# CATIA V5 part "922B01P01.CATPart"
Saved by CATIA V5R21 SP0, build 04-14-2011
Part number: 922B01P01
Bounding box of the stored display mesh (mm): x -17 to 17, y -76.2 to 76.2, z -4.3 to 4.3
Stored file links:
  C:\Users\ALI OZGUN\Desktop\alhan\922B01P01.CATPart
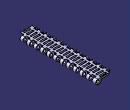
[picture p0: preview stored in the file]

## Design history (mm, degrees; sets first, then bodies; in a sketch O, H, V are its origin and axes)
Body1 (main body)
  Sketch1 on zx-plane, origin (0, 0, 0), H (-1, 0, 0), V (0, 0, 1)
    construction line L1 (-12.7, 0) -> (12.7, 0)
    point P1 (-12.7, 0)
    line L2 (-12.7, 4.3) -> (12.7, 4.3)
    line L3 (12.7, -4.3) -> (-12.7, -4.3)
    arc A1 centre (12.7, 0) radius 4.3 from (12.7, 4.3) to (12.7, -4.3) cw
    arc A2 centre (-12.7, 0) radius 4.3 from (-12.7, -4.3) to (-12.7, 4.3) cw
    distance L1 L2 = 4.3
    length L1 = 25.4
    distance P1 V = 12.7
    coincidence: P1 H
    horizontal: L1 H
    tangency: A1 L2, A2 L2, A1 L3, A2 L3
  Pad1: profile Sketch1, direction (0, 1, 0), length 76.2, mirrored extent
  Sketch2 on face of Pad1 from Sketch1.L2, origin (0, 0, 4.3), H (1, 0, 0), V (0, 1, 0)
    line L1 (-22.3127, -63.5) -> (-9.75, -63.5)
    line L2 (-9.75, -63.5) -> (-9.75, -70.6)
    line L3 (-9.75, -70.6) -> (-22.3127, -70.6)
    line L4 (-22.3127, -70.6) -> (-22.3127, -63.5)
    line L5 (24.6678, -76.95) -> (9.75, -76.95)
    line L6 (9.75, -76.95) -> (9.75, -69.85)
    line L7 (9.75, -69.85) -> (24.6678, -69.85)
    line L8 (24.6678, -69.85) -> (24.6678, -76.95)
    reference projected line E1 (-12.7, -76.2) -> (12.7, -76.2) from edge [start face of Pad1 | face of Pad1 from Sketch1.L2]
    reference projected line E2 (-12.7, -76.2) -> (12.7, -76.2) from edge [start face of Pad1 | face of Pad1 from Sketch1.L2]
    distance L3 E1 = 5.6
    length L4 = 7.1
    distance L7 L5 = 7.1
    distance L5 E2 = 0.75
    distance L2 L6 = 19.5
    distance L2 V = 9.75
    horizontal: L1 H, L3 H, L5 H, L7 H
    vertical: L2 V, L4 V, L6 V, L8 V
  Pocket1: profile Sketch2, direction (0, 0, -1), length 76.2
  RectPattern1: of Pocket1, direction 1 instances 12, spacing 12.7, along axis of face of Pad1 from Sketch1.A2
  Sketch3 on face of Pad1 from Sketch1.L3, origin (0, 0, -4.3), H (1, 0, 0), V (0, -1, 0)
    line L1 (-7, 90.4553) -> (7, 90.4553)
    line L2 (7, 90.4553) -> (7, -88.0088)
    line L3 (7, -88.0088) -> (-7, -88.0088)
    line L4 (-7, -88.0088) -> (-7, 90.4553)
    length L1 = 14
    distance L4 V = 7
    horizontal: L1 H, L3 H
    vertical: L2 V, L4 V
  Pocket2: profile Sketch3, direction (0, 0, 1), length 5.7
  Fillet1: radius 2, on edge [face of Pad1 from Sketch1.L3 | face of Pocket2 from Sketch3.L2]; edge [face of Pad1 from Sketch1.L3 | face of Pocket2 from Sketch3.L4]
  Sketch4 on yz-plane, origin (0, 0, 0), H (0, 1, 0), V (0, 0, 1)
    point P3 (69.85, -4.4)
    point P5 (69.85, -4.4)
    point P7 (57.15, -4.4)
    point P9 (57.15, -4.4)
    point P11 (44.45, -4.4)
    point P13 (44.45, -4.4)
    point P15 (31.75, -4.4)
    point P16 (31.75, -4.4)
    point P18 (19.05, -4.4)
    point P19 (19.05, 1.4)
    point P20 (19.05, -4.4)
    line L1 (-76.2, -4.4) -> (-76.2, 1.4)
    line L2 (-69.85, 1.4) -> (-69.85, -4.4)
    line L3 (-69.85, -4.4) -> (-76.2, -4.4)
    line L4 (-57.15, -4.4) -> (-64.25, -4.4)
    line L5 (-64.25, -4.4) -> (-64.25, 1.4)
    line L6 (-57.15, 1.4) -> (-57.15, -4.4)
    line L7 (-44.45, -4.4) -> (-51.55, -4.4)
    line L8 (-51.55, -4.4) -> (-51.55, 1.4)
    line L9 (-44.45, 1.4) -> (-44.45, -4.4)
    line L10 (-31.75, -4.4) -> (-38.85, -4.4)
    line L11 (-38.85, -4.4) -> (-38.85, 1.4)
    line L12 (-19.05, -4.4) -> (-26.15, -4.4)
    line L13 (-26.15, -4.4) -> (-26.15, 1.4)
    line L14 (-19.05, 1.4) -> (-19.05, -4.4)
    line L15 (-6.35, -4.4) -> (-13.45, -4.4)
    line L16 (-13.45, -4.4) -> (-13.45, 1.4)
    line L17 (-6.35, 1.4) -> (-6.35, -4.4)
    line L18 (6.35, -4.4) -> (-0.75, -4.4)
    line L19 (-0.75, -4.4) -> (-0.75, 1.4)
    line L20 (6.35, 1.4) -> (6.35, -4.4)
    construction line L21 (19.05, -4.4) -> (11.95, -4.4)
    construction line L22 (11.95, -4.4) -> (11.95, 4.4)
    construction line L23 (11.95, 4.4) -> (19.05, 4.4)
    construction line L24 (19.05, 4.4) -> (19.05, -4.4)
    line L25 (19.05, 1.4) -> (19.05, -4.4)
    line L26 (19.05, -4.4) -> (11.95, -4.4)
    line L27 (11.95, -4.4) -> (11.95, 1.4)
    construction line L28 (31.75, -4.4) -> (24.65, -4.4)
    construction line L29 (24.65, -4.4) -> (24.65, 4.4)
    construction line L30 (24.65, 4.4) -> (31.75, 4.4)
    construction line L31 (31.75, 4.4) -> (31.75, -4.4)
    line L32 (31.75, -4.4) -> (24.65, -4.4)
    line L33 (24.65, -4.4) -> (24.65, 1.4)
    line L34 (31.75, 1.4) -> (31.75, -4.4)
    construction line L35 (44.45, -4.4) -> (37.35, -4.4)
    construction line L36 (37.35, -4.4) -> (37.35, 4.4)
    construction line L37 (37.35, 4.4) -> (44.45, 4.4)
    construction line L38 (44.45, 4.4) -> (44.45, -4.4)
    line L39 (44.45, -4.4) -> (37.35, -4.4)
    line L40 (37.35, -4.4) -> (37.35, 1.4)
    line L41 (44.45, 1.4) -> (44.45, -4.4)
    construction line L42 (57.15, -4.4) -> (50.05, -4.4)
    construction line L43 (50.05, -4.4) -> (50.05, 4.4)
    construction line L44 (50.05, 4.4) -> (57.15, 4.4)
    construction line L45 (57.15, 4.4) -> (57.15, -4.4)
    line L46 (57.15, -4.4) -> (50.05, -4.4)
    line L47 (50.05, -4.4) -> (50.05, 1.4)
    line L48 (57.15, 1.4) -> (57.15, -4.4)
    construction line L49 (69.85, -4.4) -> (62.75, -4.4)
    construction line L50 (62.75, -4.4) -> (62.75, 4.4)
    construction line L51 (62.75, 4.4) -> (69.85, 4.4)
    construction line L52 (69.85, 4.4) -> (69.85, -4.4)
    line L53 (69.85, 1.4) -> (69.85, -4.4)
    line L54 (69.85, -4.4) -> (62.75, -4.4)
    line L55 (62.75, -4.4) -> (62.75, 1.4)
    construction line L56 (-76.2, 1.4) -> (76.2, 1.4)
    line L57 (62.75, 1.4) -> (69.85, 1.4)
    line L58 (50.05, 1.4) -> (57.15, 1.4)
    line L59 (37.35, 1.4) -> (44.45, 1.4)
    line L60 (-76.2, 1.4) -> (-69.85, 1.4)
    point P60 (19.05, 1.4)
    line L61 (24.65, 1.4) -> (31.75, 1.4)
    point P61 (24.65, 1.4)
    point P62 (24.65, 1.4)
    point P63 (11.95, 1.4)
    point P64 (6.35, 1.4)
    point P65 (-0.75, 1.4)
    point P66 (-6.35, 1.4)
    point P67 (-13.45, 1.4)
    point P68 (-19.05, 1.4)
    point P69 (-26.15, 1.4)
    point P70 (-38.85, 1.4)
    point P71 (-44.45, 1.4)
    point P72 (-51.55, 1.4)
    point P73 (-57.15, 1.4)
    point P74 (-64.25, 1.4)
    point P75 (-69.85, 1.4)
    line L62 (-64.25, 1.4) -> (-57.15, 1.4)
    line L63 (-51.55, 1.4) -> (-44.45, 1.4)
    line L64 (-38.85, 1.4) -> (-31.75, 1.4)
    line L65 (-26.15, 1.4) -> (-19.05, 1.4)
    line L66 (-13.45, 1.4) -> (-6.35, 1.4)
    line L67 (-0.75, 1.4) -> (6.35, 1.4)
    line L68 (11.95, 1.4) -> (19.05, 1.4)
    line L69 (-31.75, 1.4) -> (-31.75, -4.4)
    coincidence: L24 P60, L29 P61, L60 L61, L56 P62, L56 P63, L56 P64, L56 P65, L56 P66, L56 P67, L56 P68, L56 P69, L56 P70, L56 P71, L56 P72, L56 P73, L56 P74, L56 P75, L60 L62, L62 L63, L63 L64, L64 L65, L65 L66, L66 L67, L67 L68, P3 P5, P7 P9, P11 P13, P15 P16, P18 P20, P19 P60, P61 P62
    vertical: L69 V
  Pocket3: profile Sketch4, direction (1, 0, 0), length 27.8
  Sketch5 on yz-plane, origin (0, 0, 0), H (0, 1, 0), V (0, 0, 1)
    line L1 (-63.5, -4.4) -> (-70.6, -4.4)
    point P1 (-63.5, -4.4)
    point P2 (-70.6, -4.4)
    line L2 (-63.5, 1.4) -> (-63.5, -4.4)
    point P3 (-63.5, 1.4)
    point P4 (-63.5, -4.4)
    line L3 (-70.6, 1.4) -> (-63.5, 1.4)
    point P5 (-70.6, 1.4)
    point P6 (-63.5, 1.4)
    line L4 (-70.6, -4.4) -> (-70.6, 1.4)
    point P7 (-70.6, -4.4)
    point P8 (-70.6, 1.4)
    line L5 (-50.8, 1.4) -> (-50.8, -4.4)
    point P9 (-50.8, 1.4)
    point P10 (-50.8, -4.4)
    line L6 (-57.9, 1.4) -> (-50.8, 1.4)
    point P11 (-57.9, 1.4)
    point P12 (-50.8, 1.4)
    line L7 (-57.9, -4.4) -> (-57.9, 1.4)
    point P13 (-57.9, -4.4)
    point P14 (-57.9, 1.4)
    line L8 (-50.8, -4.4) -> (-57.9, -4.4)
    point P15 (-50.8, -4.4)
    point P16 (-57.9, -4.4)
    line L9 (-38.1, 1.4) -> (-38.1, -4.4)
    point P17 (-38.1, 1.4)
    point P18 (-38.1, -4.4)
    line L10 (-45.2, 1.4) -> (-38.1, 1.4)
    point P19 (-45.2, 1.4)
    point P20 (-38.1, 1.4)
    line L11 (-45.2, -4.4) -> (-45.2, 1.4)
    point P21 (-45.2, -4.4)
    point P22 (-45.2, 1.4)
    line L12 (-38.1, -4.4) -> (-45.2, -4.4)
    point P23 (-38.1, -4.4)
    point P24 (-45.2, -4.4)
    line L13 (-25.4, 1.4) -> (-25.4, -4.4)
    point P25 (-25.4, 1.4)
    point P26 (-25.4, -4.4)
    line L14 (-32.5, 1.4) -> (-25.4, 1.4)
    point P27 (-32.5, 1.4)
    point P28 (-25.4, 1.4)
    line L15 (-32.5, -4.4) -> (-32.5, 1.4)
    point P29 (-32.5, -4.4)
    point P30 (-32.5, 1.4)
    line L16 (-25.4, -4.4) -> (-32.5, -4.4)
    point P31 (-25.4, -4.4)
    point P32 (-32.5, -4.4)
    line L17 (-12.7, 1.4) -> (-12.7, -4.4)
    point P33 (-12.7, 1.4)
    point P34 (-12.7, -4.4)
    line L18 (-19.8, 1.4) -> (-12.7, 1.4)
    point P35 (-19.8, 1.4)
    point P36 (-12.7, 1.4)
    line L19 (-19.8, -4.4) -> (-19.8, 1.4)
    point P37 (-19.8, -4.4)
    point P38 (-19.8, 1.4)
    line L20 (-12.7, -4.4) -> (-19.8, -4.4)
    point P39 (-12.7, -4.4)
    point P40 (-19.8, -4.4)
    line L21 (0, 1.4) -> (0, -4.4)
    point P41 (0, 1.4)
    point P42 (0, -4.4)
    line L22 (-7.1, 1.4) -> (0, 1.4)
    point P43 (-7.1, 1.4)
    point P44 (0, 1.4)
    line L23 (-7.1, -4.4) -> (-7.1, 1.4)
    point P45 (-7.1, -4.4)
    point P46 (-7.1, 1.4)
    line L24 (0, -4.4) -> (-7.1, -4.4)
    point P47 (0, -4.4)
    point P48 (-7.1, -4.4)
    line L25 (12.7, 1.4) -> (12.7, -4.4)
    point P49 (12.7, 1.4)
    point P50 (12.7, -4.4)
    line L26 (5.6, 1.4) -> (12.7, 1.4)
    point P51 (5.6, 1.4)
    point P52 (12.7, 1.4)
    line L27 (5.6, -4.4) -> (5.6, 1.4)
    point P53 (5.6, -4.4)
    point P54 (5.6, 1.4)
    line L28 (12.7, -4.4) -> (5.6, -4.4)
    point P55 (12.7, -4.4)
    point P56 (5.6, -4.4)
    line L29 (18.3, 1.4) -> (25.4, 1.4)
    point P57 (18.3, 1.4)
    point P58 (25.4, 1.4)
    line L30 (18.3, -4.4) -> (18.3, 1.4)
    point P59 (18.3, -4.4)
    point P60 (18.3, 1.4)
    line L31 (25.4, -4.4) -> (18.3, -4.4)
    point P61 (25.4, -4.4)
    point P62 (18.3, -4.4)
    line L32 (25.4, 1.4) -> (25.4, -4.4)
    point P63 (25.4, 1.4)
    point P64 (25.4, -4.4)
    line L33 (38.1, 1.4) -> (38.1, -4.4)
    point P65 (38.1, 1.4)
    point P66 (38.1, -4.4)
    line L34 (31, 1.4) -> (38.1, 1.4)
    point P67 (31, 1.4)
    point P68 (38.1, 1.4)
    line L35 (31, -4.4) -> (31, 1.4)
    point P69 (31, -4.4)
    point P70 (31, 1.4)
    line L36 (38.1, -4.4) -> (31, -4.4)
    point P71 (38.1, -4.4)
    point P72 (31, -4.4)
    line L37 (50.8, 1.4) -> (50.8, -4.4)
    point P73 (50.8, 1.4)
    point P74 (50.8, -4.4)
    line L38 (43.7, 1.4) -> (50.8, 1.4)
    point P75 (43.7, 1.4)
    point P76 (50.8, 1.4)
    line L39 (43.7, -4.4) -> (43.7, 1.4)
    point P77 (43.7, -4.4)
    point P78 (43.7, 1.4)
    line L40 (50.8, -4.4) -> (43.7, -4.4)
    point P79 (50.8, -4.4)
    point P80 (43.7, -4.4)
    line L41 (63.5, 1.4) -> (63.5, -4.4)
    point P81 (63.5, 1.4)
    point P82 (63.5, -4.4)
    line L42 (56.4, 1.4) -> (63.5, 1.4)
    point P83 (56.4, 1.4)
    point P84 (63.5, 1.4)
    line L43 (56.4, -4.4) -> (56.4, 1.4)
    point P85 (56.4, -4.4)
    point P86 (56.4, 1.4)
    line L44 (63.5, -4.4) -> (56.4, -4.4)
    point P87 (63.5, -4.4)
    point P88 (56.4, -4.4)
    line L45 (69.1, 1.4) -> (76.2, 1.4)
    point P89 (69.1, 1.4)
    point P90 (76.2, 1.4)
    line L46 (69.1, -4.4) -> (69.1, 1.4)
    point P91 (69.1, -4.4)
    point P92 (69.1, 1.4)
    line L47 (76.2, -4.4) -> (69.1, -4.4)
    point P93 (76.2, -4.4)
    point P94 (69.1, -4.4)
    line L48 (76.2, 1.4) -> (76.2, -4.4)
    point P95 (76.2, 1.4)
    point P96 (76.2, -4.4)
    distance L2 L4 = 7.1
    distance L7 L5 = 7.1
    coincidence: P96 P93, P95 P90, P94 P91, P92 P89, P88 P85, P87 P82, P86 P83, P84 P81, P80 P77, P79 P74, P78 P75, P76 P73, P72 P69, P71 P66, P70 P67, P68 P65, P64 P61, P63 P58, P62 P59, P60 P57, P56 P53, P55 P50, P54 P51, P52 P49, P48 P45, P47 P42, P46 P43, P44 P41, P40 P37, P39 P34, P38 P35, P36 P33, P32 P29, P31 P26, P30 P27, P28 P25, P24 P21, P23 P18, P22 P19, P20 P17, P16 P13, P15 P10, P14 P11, P12 P9, P8 P5, P7 P2, P6 P3, P4 P1
    fix: L2
  Pocket4: profile Sketch5, direction (-1, 0, 0), length 27.8
  Chamfer1: length 2.5, angle 45, on edge [face of Pocket4 | face of Pocket1 from Sketch2.L6]; edge [face of Pocket4 | face of RectPattern1] (x11); edge [face of RectPattern1 | face of Pocket4] (x11); edge [face of Pocket4 | face of Pocket1 from Sketch2.L2]
  Sketch6 on zx-plane, origin (0, 0, 0), H (-1, 0, 0), V (0, 0, 1)
    circle A1 centre (12.7, 0) radius 2.3
    point P1 (12.7, 0)
    circle A2 centre (-12.7, 0) radius 2.3
    point P2 (-12.7, 0)
    reference projected arc E1 centre (12.7, 0) radius 4.3 from (12.7, -4.3) to (12.7, 4.3) ccw from edge [face of Pocket4 | face of Pad1 from Sketch1.A1]
    reference projected arc E2 centre (-12.7, 0) radius 4.3 from (-12.7, 4.3) to (-12.7, -4.3) ccw from edge [face of Pad1 from Sketch1.A2 | end face of Pad1]
    radius A1 = 2.3
    radius A2 = 2.3
    coincidence: P1 H, P2 H
    concentricity: P1 E1, A2 E2
  Pocket5: profile Sketch6, direction (0, -1, 0), length 97.8, mirrored extent
  Sketch7 on face of Pad1 from Sketch1.L2, origin (0, 0, 4.3), H (1, 0, 0), V (0, 1, 0)
    line L1 (-6.2, -71.4) -> (6.2, -71.4)
    line L2 (6.2, -71.4) -> (6.2, -74.2)
    line L3 (6.2, -74.2) -> (-6.2, -74.2)
    line L4 (-6.2, -74.2) -> (-6.2, -71.4)
    reference projected line E1 (-12.7, -76.2) -> (12.7, -76.2) from edge [start face of Pad1 | face of Pad1 from Sketch1.L2]
    line L5 (-6.2, -65.1) -> (6.2, -65.1)
    line L6 (6.2, -65.1) -> (6.2, -68.4)
    line L7 (6.2, -68.4) -> (-6.2, -68.4)
    line L8 (-6.2, -68.4) -> (-6.2, -65.1)
    distance L3 E1 = 2
    length L1 = 12.4
    distance L1 L3 = 2.8
    distance L5 L7 = 3.3
    distance L7 L1 = 3
    distance L4 V = 6.2
    horizontal: L1 H, L3 H, L5 H, L7 H
    vertical: L2 V, L4 V, L6 V, L8 V
    coincidence: L6 L2, L8 L4
  Pocket6: profile Sketch7, direction (0, 0, -1), length 5.7
  RectPattern2: of Pocket6, direction 1 instances 12, spacing 12.7, along edge [face of Pad1 from Sketch1.L2 | face of RectPattern1] reversed
Body2
  Solid1: linked copy from another document
  Translate1: Direction yz-plane, Length 25.4, ToTransfor Solid1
